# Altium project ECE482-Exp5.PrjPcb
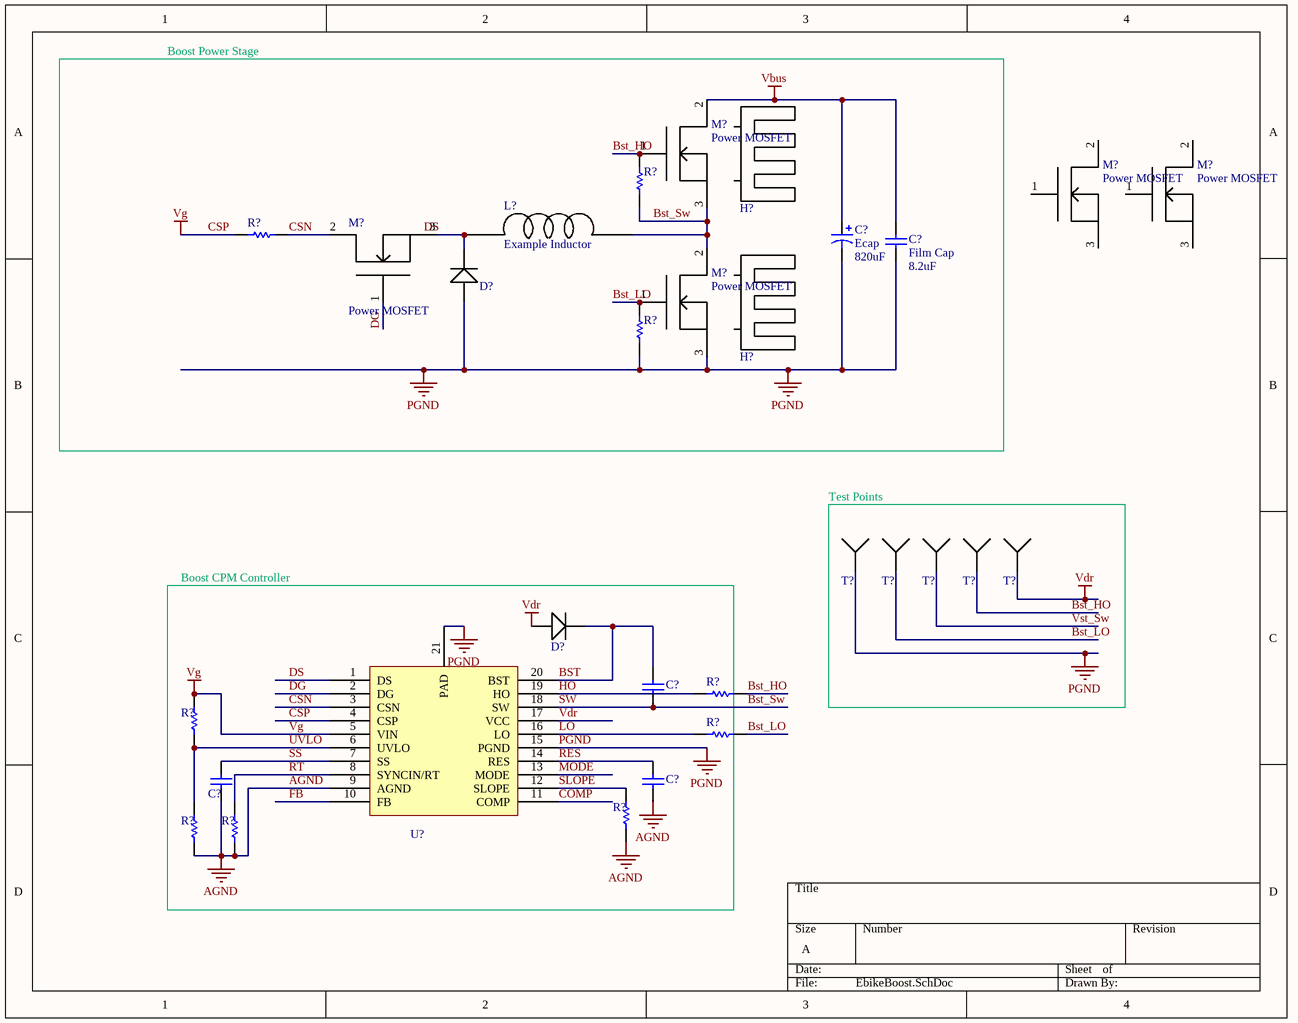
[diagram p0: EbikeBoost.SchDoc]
4 sheets, 102 parts. Net scope: global (net labels, ports and power ports of the same name join across sheets).
Board file: EbikePCB.PcbDoc
Sheets:
  EbikeBoost.SchDoc
  EbikeController.SchDoc
  EbikeMotorDriver.SchDoc
  EbikeConnectionAndProtection.SchDoc

## Sheet EbikeBoost.SchDoc
size A

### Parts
(Parts that share a designator on the sheet are numbered #1, #2 ... from top to bottom, then left to right.)
C?#1  Ecap  value 820uF  [EET-UQ2C821BA]
C?#2  Film Cap  value 8.2uF  [ECQ-E2825KF]
C?#3  Cap  [Axial C]  (value not drawn)
C?#4  Cap  [Axial C]  (value not drawn)
C?#5  Cap  [Axial C]  (value not drawn)
D?#1  Diode  [TO220-2]  (value not drawn)
D?#2  Diode  [Axial D]  (value not drawn)
H?#1  Heatsink  [Heatsink]  (value not drawn)
H?#2  Heatsink  [Heatsink]  (value not drawn)
L?  Example Inductor  [Example Inductor]
M?#1  Power MOSFET  [TO220-3]
M?#2  Power MOSFET  [TO220-3]
M?#3  Power MOSFET  [TO220-3]
M?#4  Power MOSFET  [TO220-3]
M?#5  Power MOSFET  [TO220-3]
R?#1  Res Semi  [Axial R]  (value not drawn)
R?#2  Res Semi  [Current Sense Resistor]  (value not drawn)
R?#3  Res Semi  [Axial R]  (value not drawn)
R?#4  Res Semi  [Axial R]  (value not drawn)
R?#5  Res1  [Axial R]  (value not drawn)
R?#6  Res Semi  [Axial R]  (value not drawn)
R?#7  Res1  [Axial R]  (value not drawn)
R?#8  Res1  [Axial R]  (value not drawn)
R?#9  Res1  [Axial R]  (value not drawn)
T?#1  Net  [Test Point]  (value not drawn)
T?#2  Net  [Test Point]  (value not drawn)
T?#3  Net  [Test Point]  (value not drawn)
T?#4  Net  [Test Point]  (value not drawn)
T?#5  Net  [Test Point]  (value not drawn)
U?#1  LM5121  [LM5121]  (value not drawn)

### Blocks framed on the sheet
Boost Power Stage: C?#1 C?#2 D?#1 H?#1 H?#2 L? M?#1 M?#4 M?#5 R?#1-R?#3
Test Points: T?#1-T?#5
Boost CPM Controller: C?#3-C?#5 D?#2 R?#4-R?#9 U?#1

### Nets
AGND: C?#4.1 C?#5.1 R?#7.1 R?#8.1 R?#9.1 U?#1.9(AGND)
CSP: R?#2.1 R?#5.2 U?#1.4(CSP) U?#1.5(VIN)  [also labelled Vg]
PGND: C?#1.2 C?#2.1 D?#1.1 M?#5.3(Source) R?#3.1 T?#1.1 U?#1.15(PGND) U?#1.21(PAD)
Vbus: C?#1.1 C?#2.2 M?#1.2(Drain)
Vdr: D?#2.1 T?#5.1 U?#1.17(VCC)
BST: C?#3.1 D?#2.2 U?#1.20(BST)
Bst_HO: M?#1.1(Gate) R?#1.2 R?#4.1 T?#4.1
Bst_LO: M?#5.1(Gate) R?#3.2 R?#6.1 T?#2.1
Bst_Sw: C?#3.2 L?.2 M?#1.3(Source) M?#5.2(Drain) R?#1.1 U?#1.18(SW)  [also labelled SW]
COMP: U?#1.11(COMP)
CSN: M?#4.2(Drain) R?#2.2 U?#1.3(CSN)
DG: M?#4.1(Gate) U?#1.2(DG)
DS: U?#1.1(DS)
FB: U?#1.10(FB)
HO: R?#4.2 U?#1.19(HO)
LO: R?#6.2 U?#1.16(LO)
MODE: U?#1.13(MODE)
RES: C?#5.2 U?#1.14(RES)
RT: R?#9.2 U?#1.8(SYNCIN/RT)
SLOPE: R?#7.2 U?#1.12(SLOPE)
SS: C?#4.2 U?#1.7(SS)
UVLO: R?#5.1 R?#8.2 U?#1.6(UVLO)
Vst_Sw: T?#3.1
NetD?#1_2: D?#1.2 L?.1 M?#4.3(Source)

Not connected (* = marked no-connect by the designer): H?#1 1 2; H?#2 1 2; M?#2 1(Gate) 2(Drain) 3(Source); M?#3 1(Gate) 2(Drain) 3(Source)

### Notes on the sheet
- Labels drawn without touching a wire or pin: DS

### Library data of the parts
C?#1 = Cap Pol1: Polarized Capacitor (Radial)
C?#2-C?#5 = Cap: Capacitor
H?#1 H?#2 = Heatsink: 530002B02500G
M?#1-M?#5 = Power MOSFET: Multiple
R?#1-R?#4 R?#6 = Res Semi: Semiconductor Resistor; Value: 1K
R?#5 R?#7-R?#9 = Res1: Resistor
T?#1-T?#5 = Test Point: Keystone 500(0-4) Series
U?#1 = LM5121: V/I Boost Controller With Disconnect

## Sheet EbikeController.SchDoc
size A
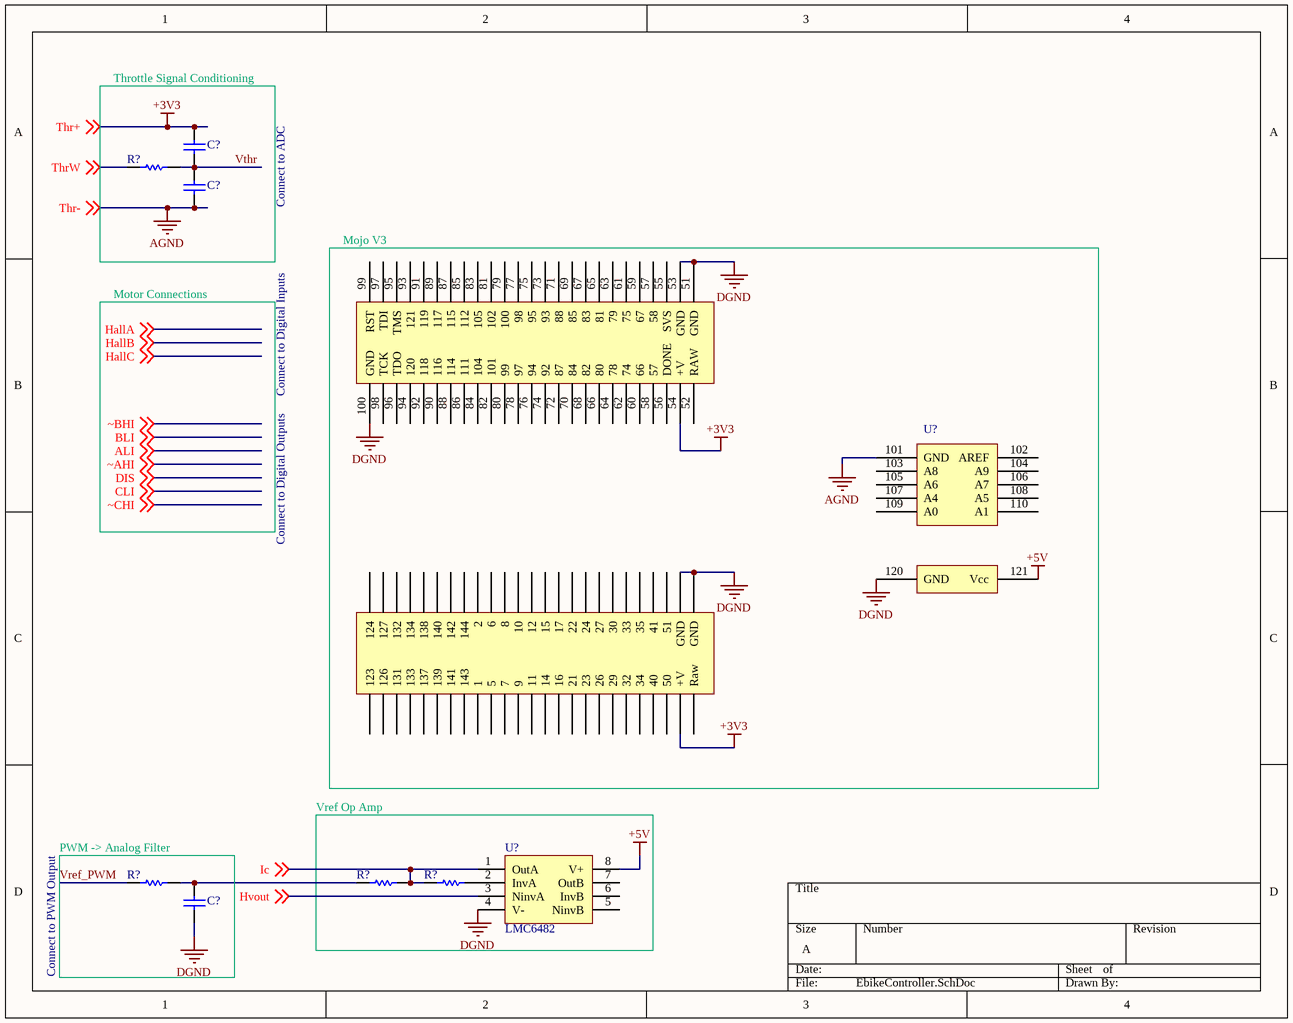
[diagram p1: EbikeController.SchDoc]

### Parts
(Parts that share a designator on the sheet are numbered #1, #2 ... from top to bottom, then left to right.)
C?#6  Cap Semi  [Axial C]  (value not drawn)
C?#7  Cap Semi  [Axial C]  (value not drawn)
C?#8  Cap Semi  [Axial C]  (value not drawn)
R?#10  Res Semi  [Axial R]  (value not drawn)
R?#11  Res Semi  [Axial R]  (value not drawn)
R?#12  Res Semi  [Axial R]  (value not drawn)
R?#13  Res Semi  [Axial R]  (value not drawn)
U?#2  Mojo V3  [Mojo V3]
U?#3  LMC6482  [DIP-8]

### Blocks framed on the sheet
Throttle Signal Conditioning: C?#6 C?#7 R?#10
Vref Op Amp: R?#12 R?#13 U?#3

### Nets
AGND: C?#7.1 U?#2.101(GND) ; off-sheet Thr-  [also labelled Thr-]
DGND: C?#8.1 U?#2.1(GND) U?#2.3(GND) U?#2.51(GND) U?#2.53(GND) U?#2.100(GND) U?#2.120(GND) U?#3.4(V-)
Thr+: C?#6.2 U?#2.4(+V) U?#2.54(+V) U?#2.121(Vcc) U?#3.8(V+) ; off-sheet Thr+  [also labelled +3V3, +5V]
Hvout: U?#3.3(NinvA) ; off-sheet Hvout
Ic: R?#12.1 R?#13.2 U?#3.1(OutA) ; off-sheet Ic
ThrW: R?#10.2 ; off-sheet ThrW
Vref_PWM: R?#11.2
Vthr: C?#6.1 C?#7.2 R?#10.1
NetC?#8_2: C?#8.2 R?#11.1 R?#12.2
NetR?#13_1: R?#13.1 U?#3.2(InvA)

Not connected (* = marked no-connect by the designer): U?#2 2(Raw) 5(51) 6(50) 7(41) 8(40) 9(35) 10(34) 11(33) 12(32) 13(30) 14(29) 15(27) 16(26) 17(24) 18(23) 19(22) 20(21) 21(17) 22(16) 23(15) 24(14) 25(12) 26(11) 27(10) 28(9) 29(8) 30(7) 31(6) 32(5) 33(2) 34(1) 35(144) 36(143) 37(142) 38(141) 39(140) 40(139) 41(138) 42(137) 43(134) 44(133) 45(132) 46(131) 47(127) 48(126) 49(124) 50(123) 52(RAW) 55(SVS) 56(DONE) 57(58) 58(57) 59(67) 60(66) 61(75) 62(74) 63(79) 64(78) 65(81) 66(80) 67(83) 68(82) 69(85) 70(84) 71(88) 72(87) 73(93) 74(92) 75(95) 76(94) 77(98) 78(97) 79(100) 80(99) 81(102) 82(101) 83(105) 84(104) 85(112) 86(111) 87(115) 88(114) 89(117) 90(116) 91(119) 92(118) 93(121) 94(120) 95(TMS) 96(TDO) 97(TDI) 98(TCK) 99(RST) 102(AREF) 103(A8) 104(A9) 105(A6) 106(A7) 107(A4) 108(A5) 109(A0) 110(A1); U?#3 5(NinvB) 6(InvB) 7(OutB)

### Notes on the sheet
- Connect to ADC
- Motor Connections
- Connect to Digital Inputs
- Connect to Digital Outputs
- PWM -> Analog Filter
- Connect to PWM Output

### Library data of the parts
C?#6-C?#8 = Cap Semi: Capacitor (Semiconductor SIM Model); Value: 100pF
R?#10-R?#13 = Res Semi: Semiconductor Resistor; Value: 1K
U?#2 = Mojo V3: FPGA + uP Dev Board
U?#3 = LMC6482: Dual Op-Amp Rail-to-Rail

## Sheet EbikeMotorDriver.SchDoc
size A
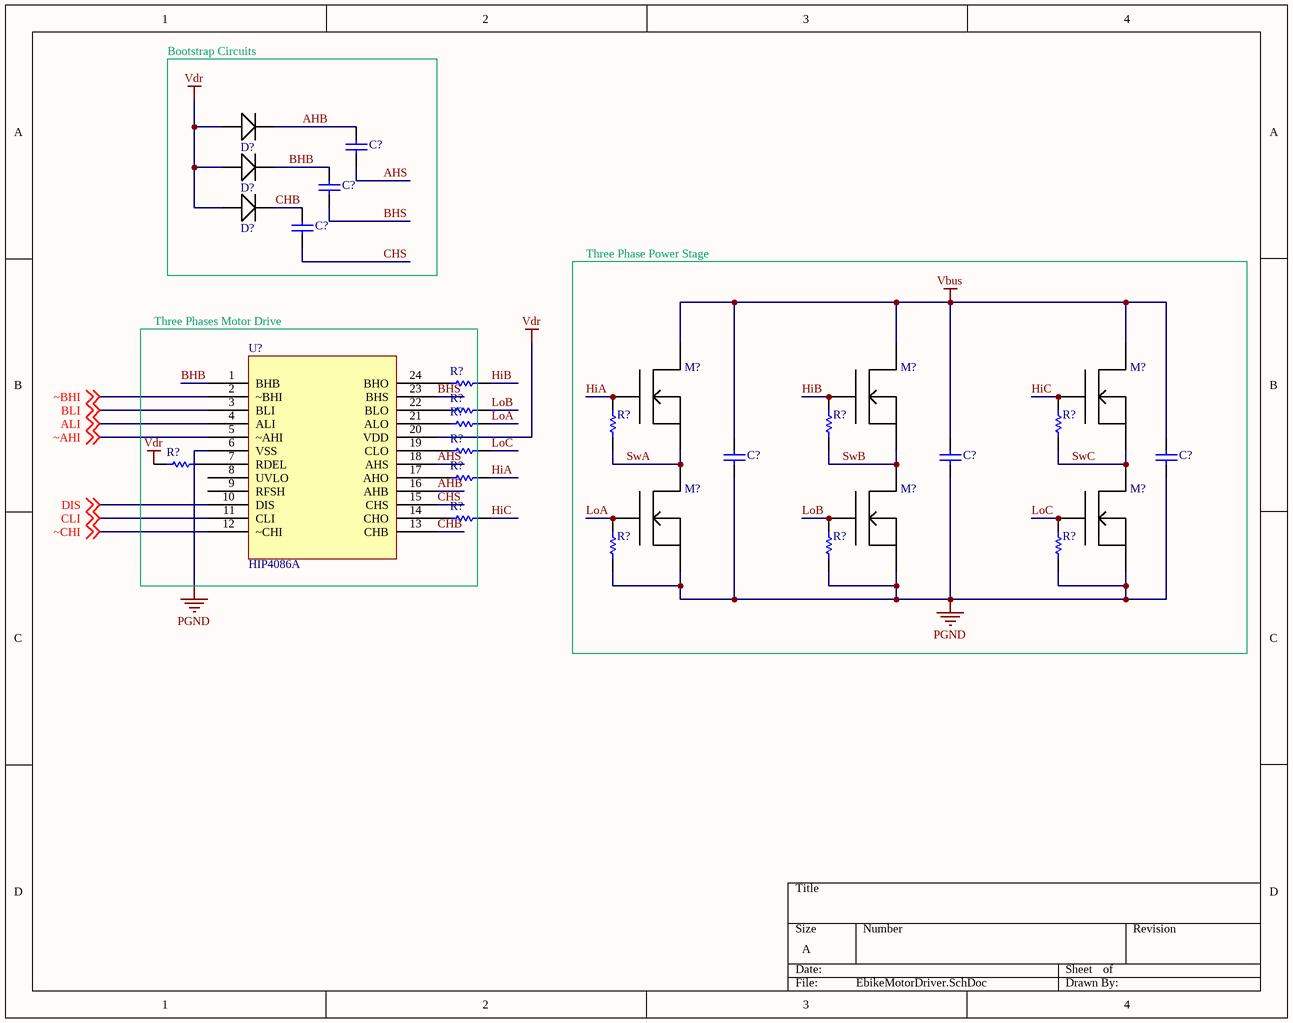
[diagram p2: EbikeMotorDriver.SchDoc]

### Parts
(Parts that share a designator on the sheet are numbered #1, #2 ... from top to bottom, then left to right.)
C?#9  Cap Semi  [Axial C]  (value not drawn)
C?#10  Cap Semi  [Axial C]  (value not drawn)
C?#11  Cap Semi  [Axial C]  (value not drawn)
C?#12  Cap Semi  [Axial C]  (value not drawn)
C?#13  Cap Semi  [Axial C]  (value not drawn)
C?#14  Cap Semi  [Axial C]  (value not drawn)
D?#3  Diode  [Axial D]  (value not drawn)
D?#4  Diode  [Axial D]  (value not drawn)
D?#5  Diode  [Axial D]  (value not drawn)
M?#6  IRFS4310  [IRFS4310]  (value not drawn)
M?#7  IRFS4310  [IRFS4310]  (value not drawn)
M?#8  IRFS4310  [IRFS4310]  (value not drawn)
M?#9  IRFS4310  [IRFS4310]  (value not drawn)
M?#10  IRFS4310  [IRFS4310]  (value not drawn)
M?#11  IRFS4310  [IRFS4310]  (value not drawn)
R?#14  Res Semi  [Axial R]  (value not drawn)
R?#15  Res Semi  [Axial R]  (value not drawn)
R?#16  Res Semi  [Axial R]  (value not drawn)
R?#17  Res Semi  [Axial R]  (value not drawn)
R?#18  Res Semi  [Axial R]  (value not drawn)
R?#19  Res Semi  [Axial R]  (value not drawn)
R?#20  Res Semi  [Axial R]  (value not drawn)
R?#21  Res Semi  [Axial R]  (value not drawn)
R?#22  Res Semi  [Axial R]  (value not drawn)
R?#23  Res Semi  [Axial R]  (value not drawn)
R?#24  Res Semi  [Axial R]  (value not drawn)
R?#25  Res Semi  [Axial R]  (value not drawn)
R?#26  Res Semi  [Axial R]  (value not drawn)
U?#4  HIP4086A  [DIP-24]

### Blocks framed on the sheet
Bootstrap Circuits: C?#9-C?#11 D?#3-D?#5
Three Phase Power Stage: C?#12-C?#14 M?#6-M?#11 R?#18-R?#20 R?#24-R?#26
Three Phases Motor Drive: R?#14-R?#17 R?#21-R?#23 U?#4

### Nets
PGND: C?#12.1 C?#13.1 C?#14.1 M?#9.3(Source) M?#10.3(Source) M?#11.3(Source) R?#24.1 R?#25.1 R?#26.1 U?#4.6(VSS)
Vbus: C?#12.2 C?#13.2 C?#14.2 M?#6.4(Drain) M?#7.4(Drain) M?#8.4(Drain)
Vdr: D?#3.1 D?#4.1 D?#5.1 R?#21.1 U?#4.20(VDD)
AHB: C?#9.2 D?#3.2 U?#4.16(AHB)
AHS: C?#9.1 U?#4.18(AHS)
ALI: U?#4.4(ALI) ; off-sheet ALI
BHB: C?#10.2 D?#4.2 U?#4.1(BHB)
BHS: C?#10.1 U?#4.23(BHS)
BLI: U?#4.3(BLI) ; off-sheet BLI
CHB: C?#11.2 D?#5.2 U?#4.13(CHB)
CHS: C?#11.1 U?#4.15(CHS)
CLI: U?#4.11(CLI) ; off-sheet CLI
DIS: U?#4.10(DIS) ; off-sheet DIS
HiA: M?#6.1(Gate) R?#18.2 R?#22.2
HiB: M?#7.1(Gate) R?#14.2 R?#19.2
HiC: M?#8.1(Gate) R?#20.2 R?#23.2
LoA: M?#9.1(Gate) R?#16.2 R?#24.2
LoB: M?#10.1(Gate) R?#15.2 R?#25.2
LoC: M?#11.1(Gate) R?#17.2 R?#26.2
SwA: M?#6.3(Source) M?#9.4(Drain) R?#18.1
SwB: M?#7.3(Source) M?#10.4(Drain) R?#19.1
SwC: M?#8.3(Source) M?#11.4(Drain) R?#20.1
~AHI: U?#4.5(~AHI) ; off-sheet ~AHI
~BHI: U?#4.2(~BHI) ; off-sheet ~BHI
~CHI: U?#4.12(~CHI) ; off-sheet ~CHI
NetR?#14_1: R?#14.1 U?#4.24(BHO)
NetR?#15_1: R?#15.1 U?#4.22(BLO)
NetR?#16_1: R?#16.1 U?#4.21(ALO)
NetR?#17_1: R?#17.1 U?#4.19(CLO)
NetR?#21_2: R?#21.2 U?#4.7(RDEL)
NetR?#22_1: R?#22.1 U?#4.17(AHO)
NetR?#23_1: R?#23.1 U?#4.14(CHO)

Not connected (* = marked no-connect by the designer): U?#4 8(UVLO) 9(RFSH)

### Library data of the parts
C?#9-C?#14 = Cap Semi: as C?#6 on sheet EbikeController
M?#6-M?#11 = IRFS4310: 100V, 120 A, 4.8 mOhm MOSFET
R?#14-R?#26 = Res Semi: Semiconductor Resistor; Value: 1K
U?#4 = HIP4086A: 3-Phase Motor Driver

## Sheet EbikeConnectionAndProtection.SchDoc
size A
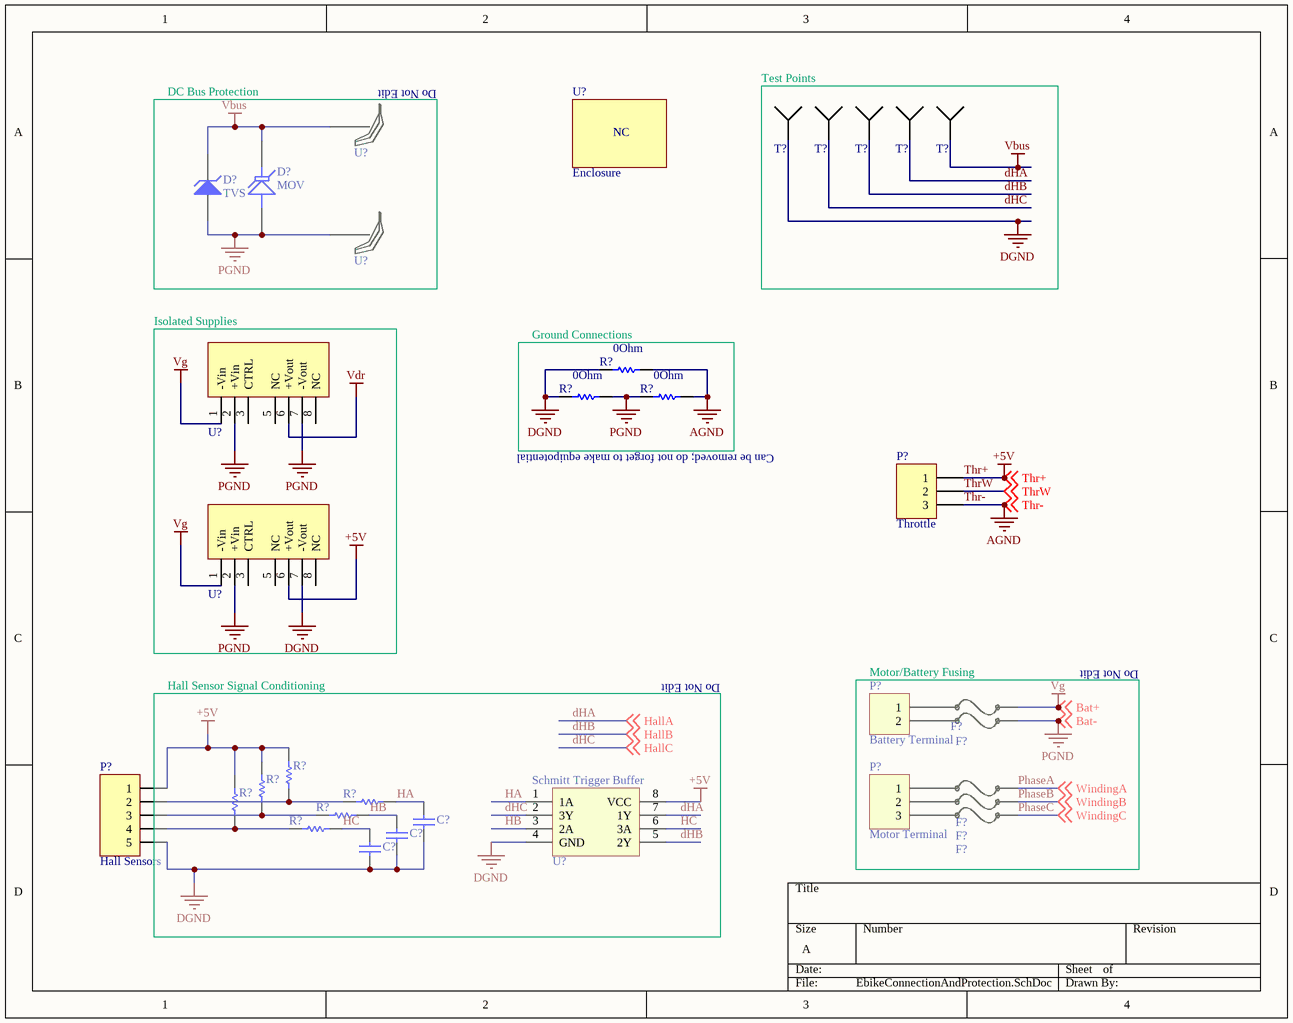
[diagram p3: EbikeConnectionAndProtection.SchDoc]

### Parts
(Parts that share a designator on the sheet are numbered #1, #2 ... from top to bottom, then left to right.)
C?#15  Cap Semi  [Axial C]  (value not drawn)
C?#16  Cap Semi  [Axial C]  (value not drawn)
C?#17  Cap Semi  [Axial C]  (value not drawn)
D?#6  TVS  [TVS]
D?#7  MOV  [MOV]
F?#1  Fuse  [Fuse Holder]  (value not drawn)
F?#2  Fuse  [Fuse Holder]  (value not drawn)
F?#3  Fuse  [Fuse Holder]  (value not drawn)
F?#4  Fuse  [Fuse Holder]  (value not drawn)
F?#5  Fuse  [Fuse Holder]  (value not drawn)
P?#1  Throttle  [Throttle Connector]
P?#2  Battery Terminal  [Battery Connector]
P?#3  Hall Sensors  [Hall Sensor Connector]
P?#4  Motor Terminal  [Motor Connector]
R?#27  0Ohm  [Axial R]
R?#28  0Ohm  [Axial R]
R?#29  0Ohm  [Axial R]
R?#30  Res Semi  [Axial R]  (value not drawn)
R?#31  Res Semi  [Axial R]  (value not drawn)
R?#32  Res Semi  [Axial R]  (value not drawn)
R?#33  Res Semi  [Axial R]  (value not drawn)
R?#34  Res Semi  [Axial R]  (value not drawn)
R?#35  Res Semi  [Axial R]  (value not drawn)
T?#6  Net  [Test Point]  (value not drawn)
T?#7  Net  [Test Point]  (value not drawn)
T?#8  Net  [Test Point]  (value not drawn)
T?#9  Net  [Test Point]  (value not drawn)
T?#10  Net  [Test Point]  (value not drawn)
U?#5  Banana Jack  [Banana Jack]  (value not drawn)
U?#6  Enclosure  [Circuit Box]
U?#7  Banana Jack  [Banana Jack]  (value not drawn)
U?#8  Iso Supply  [RSO-24xxS]  (value not drawn)
U?#9  Iso Supply  [RSO-24xxS]  (value not drawn)
U?#10  Schmitt Trigger Buffer  [PSOP-G8]

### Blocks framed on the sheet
Test Points: T?#6-T?#10
Isolated Supplies: U?#8 U?#9
Ground Connections: R?#27-R?#29

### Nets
AGND: P?#1.3 R?#27.1 R?#29.1 ; off-sheet Thr-  [also labelled Thr-]
Bat+: F?#1.2 U?#8.1(-Vin) U?#9.1(-Vin) ; off-sheet Bat+  [also labelled Vg]  [project net CSP]
DGND: C?#15.1 C?#16.1 C?#17.1 P?#3.5 R?#27.2 R?#28.2 T?#6.1 U?#9.7(-Vout) U?#10.4(GND)
PGND: D?#6.1(A) D?#7.1(A) F?#2.2 R?#28.1 R?#29.2 U?#7.1 U?#8.2(+Vin) U?#8.7(-Vout) U?#9.2(+Vin) ; off-sheet Bat-  [also labelled Bat-]
Thr+: P?#1.1 P?#3.1 R?#30.1 R?#31.1 R?#32.1 U?#9.6(+Vout) U?#10.8(VCC) ; off-sheet Thr+  [also labelled +5V]
Vbus: D?#6.2(K) D?#7.2(K) T?#10.1 U?#5.1
Vdr: U?#8.6(+Vout)
dHA: T?#9.1 U?#10.7(1Y) ; off-sheet HallA  [also labelled HallA]
dHB: T?#8.1 U?#10.5(2Y) ; off-sheet HallB  [also labelled HallB]
dHC: T?#7.1 U?#10.2(3Y) ; off-sheet HallC  [also labelled HallC]
HA: C?#15.2 R?#33.1 U?#10.1(1A)
HB: C?#16.2 R?#34.1 U?#10.3(2A)
HC: C?#17.2 R?#35.1 U?#10.6(3A)
PhaseA: F?#3.2 ; off-sheet WindingA  [also labelled WindingA]
PhaseB: F?#4.2 ; off-sheet WindingB  [also labelled WindingB]
PhaseC: F?#5.2 ; off-sheet WindingC  [also labelled WindingC]
ThrW: P?#1.2 ; off-sheet ThrW
NetF?#1_1: F?#1.1 P?#2.1
NetF?#2_1: F?#2.1 P?#2.2
NetF?#3_1: F?#3.1 P?#4.1
NetF?#4_1: F?#4.1 P?#4.2
NetF?#5_1: F?#5.1 P?#4.3
NetP?#3_2: P?#3.2 R?#30.2 R?#33.2
NetP?#3_3: P?#3.3 R?#31.2 R?#34.2
NetP?#3_4: P?#3.4 R?#32.2 R?#35.2

Not connected (* = marked no-connect by the designer): U?#8 3(CTRL) 5(NC) 8(NC); U?#9 3(CTRL) 5(NC) 8(NC)

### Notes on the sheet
- DC Bus Protection
- (near U?#5) Do Not Edit
- Can be removed; do not forget to make equipotential
- Hall Sensor Signal Conditioning
- Do Not Edit
- Motor/Battery Fusing

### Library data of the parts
C?#15-C?#17 = Cap Semi: as C?#6 on sheet EbikeController
D?#6 = D Zener: Zener Diode
D?#7 = Tranzorb
F?#1-F?#5 = Fuse: ATO/ATC .752" Fuse
P?#1 P?#4 = Header 3: Header, 3-Pin
P?#2 = Header 2: Header, 2-Pin
P?#3 = Header 5: Header, 5-Pin
R?#27-R?#35 = Res Semi: Semiconductor Resistor; Value: 1K
T?#6-T?#10 = Test Point: Keystone 500(0-4) Series
U?#5 U?#7 = Banana Jack: 575-8
U?#6 = Circuit Box
U?#8 U?#9 = Isolated Supply: RSO-24xxS
U?#10 = SN74LVC3: SN74LVC3G17DCTR

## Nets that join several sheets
AGND: EbikeBoost (6 pins), EbikeController (C?#7.1 U?#2.101), EbikeConnectionAndProtection (P?#1.3 R?#27.1 R?#29.1)
CSP: EbikeBoost (R?#2.1 R?#5.2 U?#1.4 U?#1.5), EbikeConnectionAndProtection (F?#1.2 U?#8.1 U?#9.1)
DGND: EbikeController (8 pins), EbikeConnectionAndProtection (9 pins)
PGND: EbikeBoost (8 pins), EbikeMotorDriver (10 pins), EbikeConnectionAndProtection (9 pins)
Thr+: EbikeController (5 pins), EbikeConnectionAndProtection (7 pins)
Vbus: EbikeBoost (C?#1.1 C?#2.2 M?#1.2), EbikeMotorDriver (6 pins), EbikeConnectionAndProtection (D?#6.2 D?#7.2 T?#10.1 U?#5.1)
Vdr: EbikeBoost (D?#2.1 T?#5.1 U?#1.17), EbikeMotorDriver (5 pins), EbikeConnectionAndProtection (U?#8.6)
ThrW: EbikeController (R?#10.2), EbikeConnectionAndProtection (P?#1.2)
